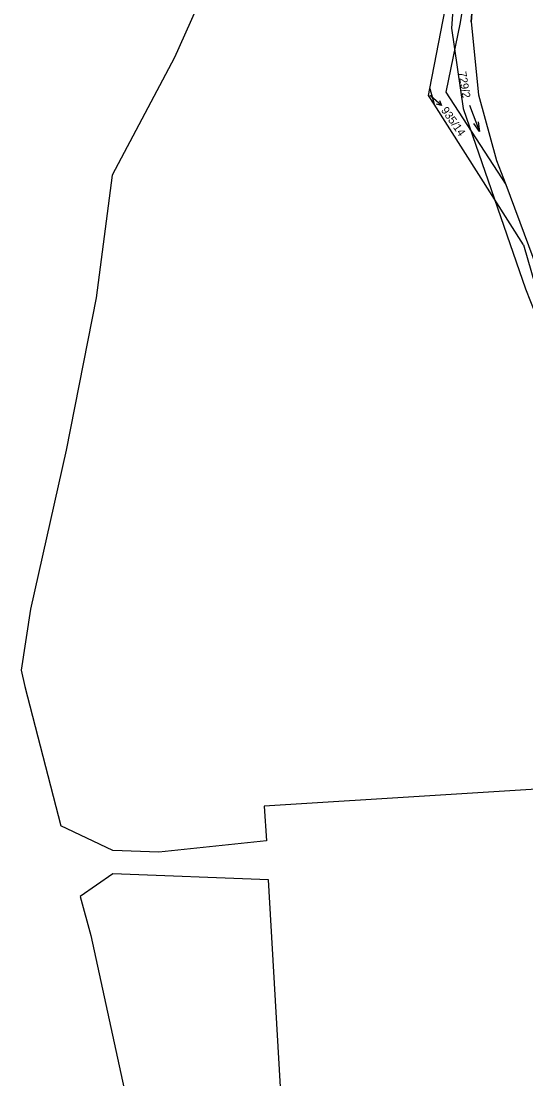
# Model space of a CAD drawing. Extents: x -580551 to -575069, y -1073031 to -1067931.
# Drawn here: x -578684 to -578576.7, y -1071266.5 to -1071041.9 of the extents above; entities that cross this region are included whole.
import ezdxf

# ---------------------------------------------------------------- set-up
doc = ezdxf.new("R2010")
doc.units = 0
for name, color, linetype in [('Druh pozemku', 7, 'Continuous'), ('Hranice státní', 7, 'Continuous'), ('Hranice z rastru', 7, 'Continuous'), ('Katastrální hranice', 7, 'Continuous'), ('Parcela', 7, 'Continuous'), ('Parcelní číslo', 7, 'Continuous'), ('Pomocná vrstva', 7, 'Continuous'), ('SR - hranice státu', 7, 'Continuous')]:
    doc.layers.add(name, color=color, linetype=linetype)

msp = doc.modelspace()

# ---------------------------------------------------------------- linework, layer by layer
at = {"layer": 'Druh pozemku'}
msp.add_line((-578588.703, -1071059.678), (-578586.557, -1071065.282), dxfattribs=at)
msp.add_lwpolyline([(-578586.806, -1071063.235), (-578586.557, -1071065.282), (-578587.739, -1071063.593)], dxfattribs=at)
at = {"layer": 'Hranice státní'}
for points in [[(-578636.54, -1070974.47), (-578641.51, -1071020.75), (-578644.45, -1071034.01), (-578651.38, -1071049.6), (-578664.66, -1071074.57), (-578668.05, -1071100.63), (-578674.45, -1071132.99), (-578681.99, -1071166.73), (-578684.01, -1071179.74), (-578683.23, -1071183.18), (-578675.56, -1071212.79)], [(-578553.56, -1071232.54), (-578556.24, -1071203.85), (-578632.3, -1071208.58), (-578631.87, -1071215.97)], [(-578631.87, -1071215.97), (-578654.76, -1071218.4), (-578664.52, -1071218.06), (-578675.56, -1071212.79)], [(-578626.17, -1071314.69), (-578631.39, -1071224.25), (-578664.54, -1071223.02), (-578671.45, -1071227.83), (-578669.19, -1071236.12), (-578650.54, -1071321.74)]]:
    msp.add_lwpolyline(points, dxfattribs=at)
at = {"layer": 'Hranice z rastru'}
msp.add_lwpolyline([(-578566.72, -1070947.779), (-578583.48, -1070998.532), (-578590.876, -1071020.93), (-578592.521, -1071043.374), (-578590.032, -1071060.419), (-578576.797, -1071098.705), (-578560.811, -1071139.089), (-578544.825, -1071179.473), (-578532.639, -1071204.254), (-578528.184, -1071216.579), (-578534.736, -1071226.806), (-578537.749, -1071239.524), (-578532.246, -1071274.139), (-578521.632, -1071309.672), (-578516.391, -1071321.603), (-578520.977, -1071339.96), (-578529.232, -1071361.069)], dxfattribs=at)
at = {"layer": 'Katastrální hranice'}
for p, q in [((-578597.1, -1071056.17), (-578588.82, -1071013.33)), ((-578597.38, -1071057.64), (-578597.1, -1071056.17)), ((-578596.18, -1071059.48), (-578597.38, -1071057.64)), ((-578577.22, -1071089.4), (-578596.18, -1071059.48)), ((-578577.22, -1071089.4), (-578571.03, -1071110.79))]:
    msp.add_line(p, q, dxfattribs=at)
at = {"layer": 'Parcela'}
for p, q in [((-578586.18, -1071013.95), (-578590.69, -1071042.14)), ((-578588.3, -1071042.01), (-578586.18, -1071013.95)), ((-578590.69, -1071042.14), (-578593.73, -1071056.97)), ((-578588.3, -1071042.01), (-578586.77, -1071057.49)), ((-578597.1, -1071056.17), (-578596.18, -1071059.48)), ((-578593.73, -1071056.97), (-578580.97, -1071076.59)), ((-578586.77, -1071057.49), (-578582.9, -1071071.43)), ((-578582.9, -1071071.43), (-578580.97, -1071076.59)), ((-578580.97, -1071076.59), (-578576.15, -1071089.49))]:
    msp.add_line(p, q, dxfattribs=at)
at = {"layer": 'Pomocná vrstva'}
for p in [(-578597.05, -1071057.67), (-578594.598, -1071059.779)]:
    msp.add_line(p, (-578596.87, -1071057.82), dxfattribs=at)
msp.add_lwpolyline([(-578595.029, -1071058.747), (-578594.598, -1071059.779), (-578595.682, -1071059.505)], dxfattribs=at)
at = {"layer": 'SR - hranice státu'}
msp.add_lwpolyline([(-578586.18, -1071013.95), (-578588.3, -1071042.01), (-578586.77, -1071057.49), (-578582.9, -1071071.43), (-578580.97, -1071076.59), (-578576.15, -1071089.49), (-578568.52, -1071109.92), (-578563.47, -1071124.19), (-578556.68, -1071143.37)], dxfattribs=at)

# ---------------------------------------------------------------- texts
at = {"layer": 'Parcelní číslo'}
for s, height, rotation, p in [('729/2', 1.7, 279.77529, (-578591.07, -1071052.702)), ('935/14', 0.1, 359.87479, (-578597.28, -1071057.669))]:
    msp.add_text(s, height=height, rotation=rotation, dxfattribs=at).set_placement(p)
at = {"layer": 'Pomocná vrstva'}
msp.add_text('935/14', height=1.7, rotation=305.21462, dxfattribs=at).set_placement((-578594.792, -1071060.794))

doc.saveas('drawing.dxf')
